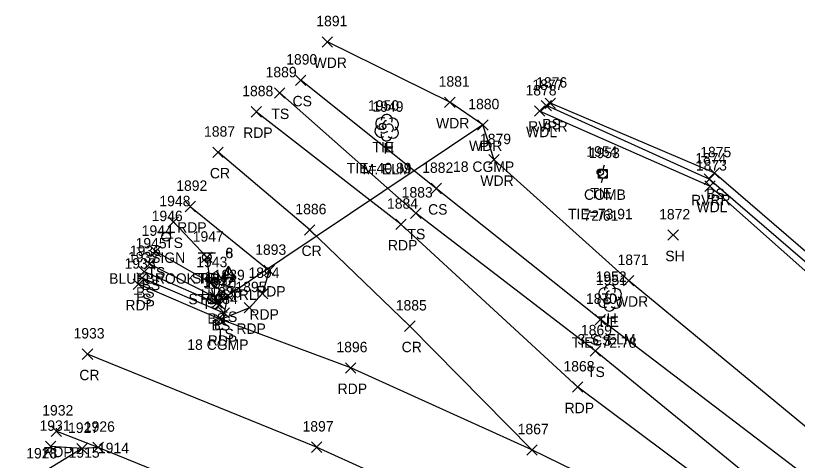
# Model space of a CAD drawing. Extents: x 1537342 to 1542195, y 163002 to 168596.
# Drawn here: x 1541534.4 to 1541684.3, y 163434.2 to 163519.5 of the extents above; entities that cross this region are included whole.
import ezdxf

# ---------------------------------------------------------------- set-up
doc = ezdxf.new("R2010")
doc.units = 0
for name, color, linetype in [('C_A', 7, 'Continuous'), ('C_C', 7, 'Continuous'), ('C_I', 7, 'Continuous'), ('CBP', 7, 'Continuous'), ('CPSM', 7, 'Continuous'), ('D_A', 7, 'Continuous'), ('D_C', 7, 'Continuous'), ('D_I', 7, 'Continuous'), ('D_TIC', 7, 'Continuous'), ('DCP', 7, 'Continuous'), ('L_A', 7, 'Continuous'), ('L_C', 7, 'Continuous'), ('L_I', 7, 'Continuous'), ('L_TIC', 7, 'Continuous'), ('LAWA', 7, 'Continuous'), ('LAWE', 7, 'Continuous'), ('LELB', 7, 'Continuous'), ('LTD', 7, 'Continuous'), ('P_A', 7, 'Continuous'), ('P_I', 7, 'Continuous'), ('P_TIC', 7, 'Continuous'), ('PET', 7, 'Continuous'), ('PRC', 7, 'Continuous'), ('R_I', 7, 'Continuous'), ('R_TIC', 7, 'Continuous'), ('RDG', 7, 'Continuous'), ('RDP', 7, 'Continuous'), ('S_A', 7, 'Continuous'), ('S_C', 7, 'Continuous'), ('S_I', 7, 'Continuous'), ('SSGN', 7, 'Continuous'), ('U_A', 7, 'Continuous'), ('U_C', 7, 'Continuous'), ('U_I', 7, 'Continuous'), ('UP', 7, 'Continuous')]:
    doc.layers.add(name, color=color, linetype=linetype)

msp = doc.modelspace()

# ---------------------------------------------------------------- linework, layer by layer
at = {"layer": 'CBP'}
for centre, radius in [((1541604.76, 163498.25), 0.625), ((1541604.76, 163498.25), 0.0833), ((1541646.53, 163489.44), 0.625), ((1541646.53, 163489.44), 0.0833), ((1541647.83, 163464.81), 0.625), ((1541647.83, 163464.81), 0.0833)]:
    msp.add_circle(centre, radius, dxfattribs=at)
at = {"layer": 'CPSM'}
for p, q in [((1541573.97, 163469.25), (1541575.22, 163471.41)), ((1541573.98, 163469.26), (1541575.23, 163471.43)), ((1541576.47, 163469.25), (1541575.22, 163471.41)), ((1541575.22, 163469.97), (1541575.22, 163471.41)), ((1541576.48, 163469.26), (1541575.23, 163471.43)), ((1541575.23, 163469.98), (1541575.23, 163471.43)), ((1541573.97, 163469.25), (1541575.22, 163469.97)), ((1541573.98, 163469.26), (1541575.23, 163469.98)), ((1541575.22, 163469.97), (1541575.22, 163469.97)), ((1541575.22, 163469.97), (1541576.47, 163469.25)), ((1541575.23, 163469.98), (1541575.23, 163469.98)), ((1541575.23, 163469.98), (1541576.48, 163469.26)), ((1541573.97, 163469.25), (1541576.47, 163469.25)), ((1541573.98, 163469.26), (1541576.48, 163469.26))]:
    msp.add_line(p, q, dxfattribs=at)
at = {"layer": 'D_TIC'}
for points in [[(1541622.99, 163497.52), (1541624.99, 163499.52)], [(1541624.99, 163497.52), (1541622.99, 163499.52)], [(1541572.02, 163463.4), (1541574.02, 163465.4)], [(1541574.02, 163463.4), (1541572.02, 163465.4)]]:
    msp.add_lwpolyline(points, dxfattribs=at)
at = {"layer": 'DCP'}
msp.add_lwpolyline([(1541623.99, 163498.52), (1541573.02, 163464.4)], dxfattribs=at)
at = {"layer": 'L_TIC'}
for points in [[(1541593.18, 163513.44), (1541595.18, 163515.44)], [(1541595.18, 163513.44), (1541593.18, 163515.44)], [(1541588.07, 163506.09), (1541590.07, 163508.09)], [(1541590.07, 163506.09), (1541588.07, 163508.09)], [(1541584.04, 163503.65), (1541586.04, 163505.65)], [(1541586.04, 163503.65), (1541584.04, 163505.65)], [(1541616.66, 163501.86), (1541618.66, 163503.86)], [(1541618.66, 163501.86), (1541616.66, 163503.86)], [(1541635.18, 163501.23), (1541637.18, 163503.23)], [(1541637.18, 163501.23), (1541635.18, 163503.23)], [(1541635.96, 163501.67), (1541637.96, 163503.67)], [(1541637.96, 163501.67), (1541635.96, 163503.67)], [(1541633.88, 163500.17), (1541635.88, 163502.17)], [(1541635.88, 163500.17), (1541633.88, 163502.17)], [(1541622.99, 163497.52), (1541624.99, 163499.52)], [(1541624.99, 163497.52), (1541622.99, 163499.52)], [(1541625.15, 163490.84), (1541627.15, 163492.84)], [(1541627.15, 163490.84), (1541625.15, 163492.84)], [(1541666.42, 163487.13), (1541668.42, 163489.13)], [(1541668.42, 163487.13), (1541666.42, 163489.13)], [(1541667.38, 163488.32), (1541669.38, 163490.32)], [(1541669.38, 163488.32), (1541667.38, 163490.32)], [(1541666.55, 163485.78), (1541668.55, 163487.78)], [(1541668.55, 163485.78), (1541666.55, 163487.78)], [(1541614.06, 163485.33), (1541616.06, 163487.33)], [(1541616.06, 163485.33), (1541614.06, 163487.33)], [(1541610.14, 163480.6), (1541612.14, 163482.6)], [(1541612.14, 163480.6), (1541610.14, 163482.6)], [(1541563.66, 163478.93), (1541565.66, 163480.93)], [(1541565.66, 163478.93), (1541563.66, 163480.93)], [(1541659.5, 163476.4), (1541661.5, 163478.4)], [(1541661.5, 163476.4), (1541659.5, 163478.4)], [(1541560.27, 163473.26), (1541562.27, 163475.26)], [(1541562.27, 163473.26), (1541560.27, 163475.26)], [(1541570.06, 163472.14), (1541572.06, 163474.14)], [(1541572.06, 163472.14), (1541570.06, 163474.14)], [(1541559.11, 163470.85), (1541561.11, 163472.85)], [(1541561.11, 163470.85), (1541559.11, 163472.85)], [(1541558.05, 163469.4), (1541560.05, 163471.4)], [(1541560.05, 163469.4), (1541558.05, 163471.4)], [(1541557.64, 163468.18), (1541559.64, 163470.18)], [(1541559.64, 163468.18), (1541557.64, 163470.18)], [(1541650.96, 163467.67), (1541652.96, 163469.67)], [(1541652.96, 163467.67), (1541650.96, 163469.67)], [(1541570.74, 163467.25), (1541572.74, 163469.25)], [(1541572.74, 163467.25), (1541570.74, 163469.25)], [(1541570.74, 163467.25), (1541572.74, 163469.25)], [(1541572.74, 163467.25), (1541570.74, 163469.25)], [(1541574.09, 163464.75), (1541576.09, 163466.75)], [(1541576.09, 163464.75), (1541574.09, 163466.75)], [(1541571.73, 163464.43), (1541573.73, 163466.43)], [(1541573.73, 163464.43), (1541571.73, 163466.43)], [(1541572.54, 163463.12), (1541574.54, 163465.12)], [(1541574.54, 163463.12), (1541572.54, 163465.12)], [(1541573.43, 163461.45), (1541575.43, 163463.45)], [(1541575.43, 163461.45), (1541573.43, 163463.45)], [(1541645.55, 163460.21), (1541647.55, 163462.21)], [(1541647.55, 163460.21), (1541645.55, 163462.21)], [(1541644.56, 163454.19), (1541646.56, 163456.19)], [(1541646.56, 163454.19), (1541644.56, 163456.19)]]:
    msp.add_lwpolyline(points, dxfattribs=at)
at = {"layer": 'LAWA'}
for points in [[(1541858.3, 163366.25), (1541851.23, 163367.97), (1541844.34, 163370.6), (1541815.36, 163382.31), (1541797.41, 163395.47), (1541778.64, 163400.7), (1541758.29, 163411.82), (1541723.78, 163418.04), (1541697.04, 163431.45), (1541651.96, 163468.67), (1541626.15, 163491.84), (1541623.99, 163498.52), (1541617.66, 163502.86), (1541594.18, 163514.44)], [(1541858.3, 163366.25), (1541879.51, 163370.15), (1541893.62, 163370.51), (1541908.1, 163373.66), (1541889.78, 163380.93), (1541869.01, 163392.19), (1541846.9, 163401.17), (1541820.74, 163408.53), (1541800.16, 163418.36), (1541771.31, 163422.69), (1541733.43, 163438.83), (1541707.98, 163450.9), (1541667.55, 163486.78), (1541634.88, 163501.17)]]:
    msp.add_lwpolyline(points, dxfattribs=at)
at = {"layer": 'LAWE'}
msp.add_lwpolyline([(1541807.79, 163344.41), (1541817.37, 163345.92), (1541838.27, 163351.14), (1541849.61, 163357.05), (1541859.07, 163364.08), (1541878.93, 163368.69), (1541894.03, 163369.19), (1541909.94, 163373.2), (1541909.62, 163375.47), (1541892.25, 163384.66), (1541871.9, 163398.76), (1541848.11, 163410.16), (1541823.72, 163419.67), (1541801.87, 163424.04), (1541777.04, 163426.76), (1541733.23, 163439.48), (1541709.17, 163452.19), (1541667.42, 163488.13), (1541636.18, 163502.23)], dxfattribs=at)
at = {"layer": 'LELB'}
for points in [[(1541813.12, 163355.49), (1541807.59, 163352.29), (1541792.75, 163363.67), (1541773.45, 163377.86), (1541766.85, 163384.06), (1541755.11, 163388.66), (1541717.31, 163411.39), (1541693.13, 163425.74), (1541646.55, 163461.21), (1541615.06, 163486.33), (1541589.07, 163507.09)], [(1541806.46, 163346.35), (1541770.85, 163375.53), (1541766.11, 163382.32), (1541753.11, 163384.46), (1541712.96, 163403.65), (1541689.28, 163419.49), (1541645.56, 163455.19), (1541611.14, 163481.6), (1541585.04, 163504.65)], [(1541710.21, 163453.27), (1541668.38, 163489.32), (1541636.96, 163502.67)], [(1541571.74, 163468.25), (1541571.06, 163473.14), (1541564.66, 163479.93)], [(1541558.64, 163469.18), (1541574.43, 163462.45), (1541575.09, 163465.75), (1541571.74, 163468.25), (1541561.27, 163474.26)], [(1541559.05, 163470.4), (1541573.54, 163464.12), (1541572.73, 163465.43), (1541560.11, 163471.85)]]:
    msp.add_lwpolyline(points, dxfattribs=at)
at = {"layer": 'LTD'}
for p, q in [((1541605.53, 163498.04), (1541605.53, 163498.04)), ((1541605.53, 163498.04), (1541605.53, 163498.04)), ((1541648.3, 163465.43), (1541648.3, 163465.43)), ((1541648.3, 163465.43), (1541648.3, 163465.43))]:
    msp.add_line(p, q, dxfattribs=at)
for centre in [(1541605.58, 163499.47), (1541648.35, 163466.86)]:
    msp.add_arc(centre, 1.05, 335.5272, 180.9563, dxfattribs=at)
for centre, major_axis, ratio, start_param, end_param in [((1541604.74, 163498.71), (1.21, -0.51), 0.895232, 1.570796, 4.712389), ((1541606.58, 163498.62), (-1.14, -0.48), 0.949671, 1.570796, 4.712389), ((1541604.45, 163497.33), (0.58, -1.04), 0.959034, 3.141593, 6.283185), ((1541605.33, 163498.5), (-0.208, -0.792), 0.645439, 3.141593, 6.283185), ((1541606.03, 163497.87), (-0.5, 0.667), 0.989748, 3.141593, 6.283185), ((1541606.53, 163497.21), (-1.09, 0.79), 0.841452, 1.570796, 4.712389), ((1541605.53, 163496.54), (0.26, 1.06), 0.942809, 1.570796, 4.712389), ((1541605.08, 163497.29), (-0.625, -0.083), 0.423636, 0, 3.141593), ((1541647.51, 163466.1), (1.21, -0.51), 0.895232, 1.570796, 4.712389), ((1541648.09, 163465.89), (-0.208, -0.792), 0.645439, 3.141593, 6.283185), ((1541649.34, 163466.01), (-1.14, -0.48), 0.949671, 1.570796, 4.712389), ((1541647.22, 163464.72), (0.58, -1.04), 0.959034, 3.141593, 6.283185), ((1541648.8, 163465.26), (-0.5, 0.667), 0.989748, 3.141593, 6.283185), ((1541649.3, 163464.6), (-1.09, 0.79), 0.841452, 1.570796, 4.712389), ((1541648.3, 163463.93), (0.26, 1.06), 0.942809, 1.570796, 4.712389), ((1541647.84, 163464.68), (-0.625, -0.083), 0.423636, 0, 3.141593)]:
    msp.add_ellipse(centre, major_axis=major_axis, ratio=ratio, start_param=start_param, end_param=end_param, dxfattribs=at)
at = {"layer": 'P_TIC'}
for points in [[(1541579.56, 163500.03), (1541581.56, 163502.03)], [(1541581.56, 163500.03), (1541579.56, 163502.03)], [(1541572.23, 163492.27), (1541574.23, 163494.27)], [(1541574.23, 163492.27), (1541572.23, 163494.27)], [(1541566.89, 163481.88), (1541568.89, 163483.88)], [(1541568.89, 163481.88), (1541566.89, 163483.88)], [(1541607.31, 163478.46), (1541609.31, 163480.46)], [(1541609.31, 163478.46), (1541607.31, 163480.46)], [(1541589.8, 163477.39), (1541591.8, 163479.39)], [(1541591.8, 163477.39), (1541589.8, 163479.39)], [(1541582.03, 163469.62), (1541584.03, 163471.62)], [(1541584.03, 163469.62), (1541582.03, 163471.62)], [(1541556.97, 163466.97), (1541558.97, 163468.97)], [(1541558.97, 163466.97), (1541556.97, 163468.97)], [(1541580.74, 163465.19), (1541582.74, 163467.19)], [(1541582.74, 163465.19), (1541580.74, 163467.19)], [(1541578.24, 163462.47), (1541580.24, 163464.47)], [(1541580.24, 163462.47), (1541578.24, 163464.47)], [(1541572.75, 163460.19), (1541574.75, 163462.19)], [(1541574.75, 163460.19), (1541572.75, 163462.19)], [(1541572.75, 163460.19), (1541574.75, 163462.19)], [(1541574.75, 163460.19), (1541572.75, 163462.19)], [(1541608.99, 163458.95), (1541610.99, 163460.95)], [(1541610.99, 163458.95), (1541608.99, 163460.95)], [(1541547.19, 163453.58), (1541549.19, 163455.58)], [(1541549.19, 163453.58), (1541547.19, 163455.58)], [(1541597.66, 163450.94), (1541599.66, 163452.94)], [(1541599.66, 163450.94), (1541597.66, 163452.94)], [(1541641.2, 163447.26), (1541643.2, 163449.26)], [(1541643.2, 163447.26), (1541641.2, 163449.26)], [(1541541.2, 163438.81), (1541543.2, 163440.81)], [(1541543.2, 163438.81), (1541541.2, 163440.81)], [(1541549.23, 163435.7), (1541551.23, 163437.7)], [(1541551.23, 163435.7), (1541549.23, 163437.7)], [(1541591.11, 163435.74), (1541593.11, 163437.74)], [(1541593.11, 163435.74), (1541591.11, 163437.74)], [(1541632.42, 163435.22), (1541634.42, 163437.22)], [(1541634.42, 163435.22), (1541632.42, 163437.22)], [(1541632.42, 163435.22), (1541634.42, 163437.22)], [(1541634.42, 163435.22), (1541632.42, 163437.22)]]:
    msp.add_lwpolyline(points, dxfattribs=at)
at = {"layer": 'PET'}
for points in [[(1541702.01, 163402.19), (1541687.22, 163414.66), (1541642.2, 163448.26), (1541608.31, 163479.46), (1541580.56, 163501.03)], [(1541567.89, 163482.88), (1541583.03, 163470.62), (1541581.74, 163466.19), (1541579.24, 163463.47), (1541573.75, 163461.19)], [(1541804.88, 163343.94), (1541781.94, 163357.9), (1541762.27, 163369.13), (1541719.07, 163393.38), (1541702.01, 163402.19), (1541685.47, 163410.81), (1541633.42, 163436.22), (1541598.66, 163451.94), (1541573.75, 163461.19), (1541557.97, 163467.97)], [(1541804.88, 163343.94), (1541786.3, 163336.28), (1541767.14, 163328.63), (1541744.37, 163342.88), (1541704.8, 163365.13), (1541670.45, 163382.89), (1541617.1, 163408.36), (1541585.57, 163422.3), (1541550.23, 163436.7), (1541542.2, 163439.81)]]:
    msp.add_lwpolyline(points, dxfattribs=at)
at = {"layer": 'PRC'}
for points in [[(1541633.42, 163436.22), (1541609.99, 163459.95), (1541590.8, 163478.39), (1541573.23, 163493.27)], [(1541786.3, 163336.28), (1541753.03, 163356.38), (1541711.83, 163379.06), (1541677.63, 163397.19), (1541623.38, 163422.53), (1541592.11, 163436.74), (1541548.19, 163454.58)]]:
    msp.add_lwpolyline(points, dxfattribs=at)
at = {"layer": 'R_TIC'}
for points in [[(1541540.1, 163435.88), (1541542.1, 163437.88)], [(1541542.1, 163435.88), (1541540.1, 163437.88)], [(1541546.15, 163435.47), (1541548.15, 163437.47)], [(1541548.15, 163435.47), (1541546.15, 163437.47)], [(1541546.15, 163435.47), (1541548.15, 163437.47)], [(1541548.15, 163435.47), (1541546.15, 163437.47)], [(1541549.23, 163435.7), (1541551.23, 163437.7)], [(1541551.23, 163435.7), (1541549.23, 163437.7)]]:
    msp.add_lwpolyline(points, dxfattribs=at)
at = {"layer": 'RDG'}
msp.add_lwpolyline([(1541547.15, 163436.47), (1541539.12, 163431.58), (1541534.4, 163420.43), (1541534.58, 163392.9)], dxfattribs=at)
at = {"layer": 'RDP'}
msp.add_lwpolyline([(1541550.23, 163436.7), (1541547.15, 163436.47), (1541541.1, 163436.88)], dxfattribs=at)
at = {"layer": 'SSGN'}
for p, q in [((1541561.61, 163477.94), (1541564.94, 163477.94)), ((1541563.26, 163477.1), (1541563.26, 163477.1)), ((1541569.43, 163473.99), (1541572.76, 163473.99)), ((1541571.08, 163473.16), (1541571.08, 163473.16))]:
    msp.add_line(p, q, dxfattribs=at)
for centre in [(1541563.26, 163477.1), (1541571.08, 163473.16)]:
    msp.add_circle(centre, 0.833, dxfattribs=at)
at = {"layer": 'UP'}
for p, q in [((1541647.26, 163490.82), (1541647.01, 163489.99)), ((1541646.18, 163488.32), (1541646.18, 163489.99)), ((1541646.18, 163489.99), (1541647.85, 163489.99)), ((1541647.01, 163489.16), (1541647.01, 163489.16)), ((1541647.85, 163489.99), (1541647.85, 163488.32)), ((1541647.85, 163488.32), (1541646.18, 163488.32)), ((1541646.76, 163487.49), (1541647.01, 163488.32))]:
    msp.add_line(p, q, dxfattribs=at)
msp.add_circle((1541647.01, 163489.16), 0.833, dxfattribs=at)

# ---------------------------------------------------------------- texts
at = {"layer": 'C_A'}
for s, p in [('TIE', (1541602.83, 163493.25)), ('TIE', (1541644.61, 163484.44)), ('HVCTRL', (1541569.91, 163464.97)), ('HVCTRL', (1541569.92, 163464.98)), ('TIE', (1541645.91, 163459.81))]:
    msp.add_text(s, height=2, dxfattribs=at).set_placement(p)
at = {"layer": 'C_C'}
for s, p in [('TIE=40.89', (1541597.9, 163489.25)), ('TIE=73.91', (1541640.33, 163480.44)), ('TIE=72.78', (1541641.06, 163455.81))]:
    msp.add_text(s, height=2, dxfattribs=at).set_placement(p)
at = {"layer": 'C_I'}
for s, p in [('1950', (1541601.98, 163501.25)), ('1954', (1541643.84, 163492.44)), ('6', (1541574.6, 163472.97)), ('8', (1541574.66, 163472.98)), ('1951', (1541645.7, 163467.81))]:
    msp.add_text(s, height=2, dxfattribs=at).set_placement(p)
at = {"layer": 'D_A'}
for p in [(1541623.37, 163493.52), (1541572.4, 163459.4)]:
    msp.add_text('P', height=2, dxfattribs=at).set_placement(p)
at = {"layer": 'D_C'}
for p in [(1541618.28, 163489.52), (1541567.32, 163455.4)]:
    msp.add_text('18 CGMP', height=2, dxfattribs=at).set_placement(p)
at = {"layer": 'D_I'}
for s, p in [('1880', (1541621.21, 163501.52)), ('1942', (1541570.33, 163467.4))]:
    msp.add_text(s, height=2, dxfattribs=at).set_placement(p)
at = {"layer": 'L_A'}
for s, p in [('WDR', (1541591.54, 163509.44)), ('CS', (1541587.51, 163502.09)), ('TS', (1541583.45, 163499.65)), ('WDR', (1541615.02, 163497.86)), ('BS', (1541635.4, 163497.67)), ('WDL', (1541632.3, 163496.17)), ('RVRR', (1541632.69, 163497.23)), ('H', (1541604.97, 163493.04)), ('WDR', (1541621.35, 163493.52)), ('WDR', (1541623.52, 163486.84)), ('BS', (1541666.82, 163484.32)), ('RVRR', (1541663.93, 163483.13)), ('CS', (1541613.5, 163481.33)), ('WDL', (1541664.96, 163481.78)), ('TS', (1541609.55, 163476.6)), ('TS', (1541563.07, 163474.93)), ('SH', (1541658.99, 163472.4)), ('TS', (1541559.68, 163469.26)), ('TS', (1541569.47, 163468.14)), ('BS', (1541558.55, 163466.85)), ('BS', (1541557.49, 163465.4)), ('TS', (1541557.05, 163464.18)), ('TS', (1541570.15, 163463.25)), ('TS', (1541570.15, 163463.25)), ('WDR', (1541649.32, 163463.67)), ('BS', (1541571.17, 163460.43)), ('TS', (1541573.5, 163460.75)), ('H', (1541647.73, 163460.43)), ('BS', (1541571.98, 163459.12)), ('TS', (1541572.84, 163457.45)), ('CS', (1541644.99, 163456.21)), ('TS', (1541643.97, 163450.19))]:
    msp.add_text(s, height=2, dxfattribs=at).set_placement(p)
at = {"layer": 'L_C'}
for s, p in [('M. ELM', (1541600.95, 163489.04)), ('3-S. ELM', (1541642.13, 163456.43))]:
    msp.add_text(s, height=2, dxfattribs=at).set_placement(p)
at = {"layer": 'L_I'}
for s, p in [('1891', (1541592.06, 163517.44)), ('1890', (1541586.29, 163510.09)), ('1889', (1541582.34, 163507.65)), ('1881', (1541615.53, 163505.86)), ('1877', (1541633.49, 163505.23)), ('1876', (1541634.22, 163505.67)), ('1878', (1541632.19, 163504.17)), ('1949', (1541602.83, 163501.04)), ('1880', (1541621.21, 163501.52)), ('1879', (1541623.45, 163494.84)), ('1875', (1541665.69, 163492.32)), ('1874', (1541664.73, 163491.13)), ('1882', (1541612.37, 163489.33)), ('1873', (1541664.85, 163489.78)), ('1883', (1541608.44, 163484.6)), ('1948', (1541561.97, 163482.93)), ('1872', (1541657.81, 163480.4)), ('1944', (1541558.58, 163477.26)), ('1947', (1541568.36, 163476.14)), ('1945', (1541557.41, 163474.85)), ('1937', (1541555.95, 163472.18)), ('1936', (1541556.3, 163473.4)), ('1943', (1541569.05, 163471.25)), ('1943', (1541569.05, 163471.25)), ('1871', (1541649.83, 163471.67)), ('1941', (1541570.6, 163468.43)), ('1939', (1541572.39, 163468.75)), ('1952', (1541645.61, 163468.43)), ('1940', (1541570.76, 163467.12)), ('1938', (1541571.74, 163465.45)), ('1870', (1541643.77, 163464.21)), ('1869', (1541642.81, 163458.19)), ('1915', (1541544.56, 163434.72)), ('1915', (1541544.56, 163434.72)), ('1914', (1541550.18, 163435.58))]:
    msp.add_text(s, height=2, dxfattribs=at).set_placement(p)
at = {"layer": 'P_A'}
for s, p in [('RDP', (1541578.04, 163496.03)), ('CR', (1541571.66, 163488.27)), ('RDP', (1541565.38, 163477.88)), ('RDP', (1541605.8, 163474.46)), ('CR', (1541589.23, 163473.39)), ('RDP', (1541580.52, 163465.62)), ('RDP', (1541555.46, 163462.97)), ('RDP', (1541579.23, 163461.19)), ('RDP', (1541576.73, 163458.47)), ('RDP', (1541571.24, 163456.19)), ('RDP', (1541571.24, 163456.19)), ('CR', (1541608.43, 163454.95)), ('CR', (1541546.62, 163449.58)), ('RDP', (1541596.15, 163446.94)), ('RDP', (1541639.68, 163443.26)), ('RDP', (1541539.69, 163434.81))]:
    msp.add_text(s, height=2, dxfattribs=at).set_placement(p)
at = {"layer": 'P_I'}
for s, p in [('1888', (1541577.86, 163504.03)), ('1887', (1541570.53, 163496.27)), ('1892', (1541565.2, 163485.88)), ('1884', (1541605.62, 163482.46)), ('1886', (1541588.05, 163481.39)), ('1893', (1541580.34, 163473.62)), ('1935', (1541555.28, 163470.97)), ('1894', (1541579.05, 163469.19)), ('1895', (1541576.55, 163466.47)), ('1934', (1541571.06, 163464.19)), ('1934', (1541571.06, 163464.19)), ('1885', (1541607.3, 163462.95)), ('1933', (1541545.5, 163457.58)), ('1896', (1541595.92, 163454.94)), ('1868', (1541639.46, 163451.26)), ('1932', (1541539.51, 163442.81)), ('1926', (1541547.48, 163439.7)), ('1897', (1541589.42, 163439.74)), ('1867', (1541630.68, 163439.22)), ('1867', (1541630.68, 163439.22))]:
    msp.add_text(s, height=2, dxfattribs=at).set_placement(p)
at = {"layer": 'R_I'}
for s, p in [('1931', (1541538.98, 163439.88)), ('1927', (1541544.45, 163439.47)), ('1927', (1541544.45, 163439.47)), ('1926', (1541547.48, 163439.7)), ('1928', (1541536.43, 163434.58))]:
    msp.add_text(s, height=2, dxfattribs=at).set_placement(p)
at = {"layer": 'S_A'}
for p in [(1541560.39, 163472.08), (1541568.21, 163468.14)]:
    msp.add_text('SIGN', height=2, dxfattribs=at).set_placement(p)
at = {"layer": 'S_C'}
for s, p in [('BLUEBROOK RD', (1541552.33, 163468.08)), ('STOP', (1541567.54, 163464.14))]:
    msp.add_text(s, height=2, dxfattribs=at).set_placement(p)
at = {"layer": 'S_I'}
for s, p in [('1946', (1541560.49, 163480.08)), ('1947', (1541568.36, 163476.14))]:
    msp.add_text(s, height=2, dxfattribs=at).set_placement(p)
at = {"layer": 'U_A'}
msp.add_text('COMB', height=2, dxfattribs=at).set_placement((1541643.4, 163484.16))
at = {"layer": 'U_C'}
msp.add_text('72/61', height=2, dxfattribs=at).set_placement((1541643.3, 163480.16))
at = {"layer": 'U_I'}
msp.add_text('1953', height=2, dxfattribs=at).set_placement((1541644.32, 163492.16))

doc.saveas('drawing.dxf')
